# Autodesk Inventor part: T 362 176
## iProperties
Created: 2005-06
Part Number: T 362 176
Material: 6PA45/1GF30
Document SubType Name: Modeling
Designer: I.Baliuc
Manufacturer: Standard
Standards Organization: Custom
Description: Schutzkappe
Density: 0.94 g/cm^3
Title: Schutzkappe
Company: Mayer & Müller AG Schaltgeräte
Abmessung: Granulat
Zweck: Ü - Schalter
Author: T.Messerschmitt
Revision Number: 362176
Keywords: 384043
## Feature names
1. Drehung1 [Revolution]
2. Fase1 [Chamfer]
3. Extrusion1
4. Runde Anordnung1 [Circular Pattern]
